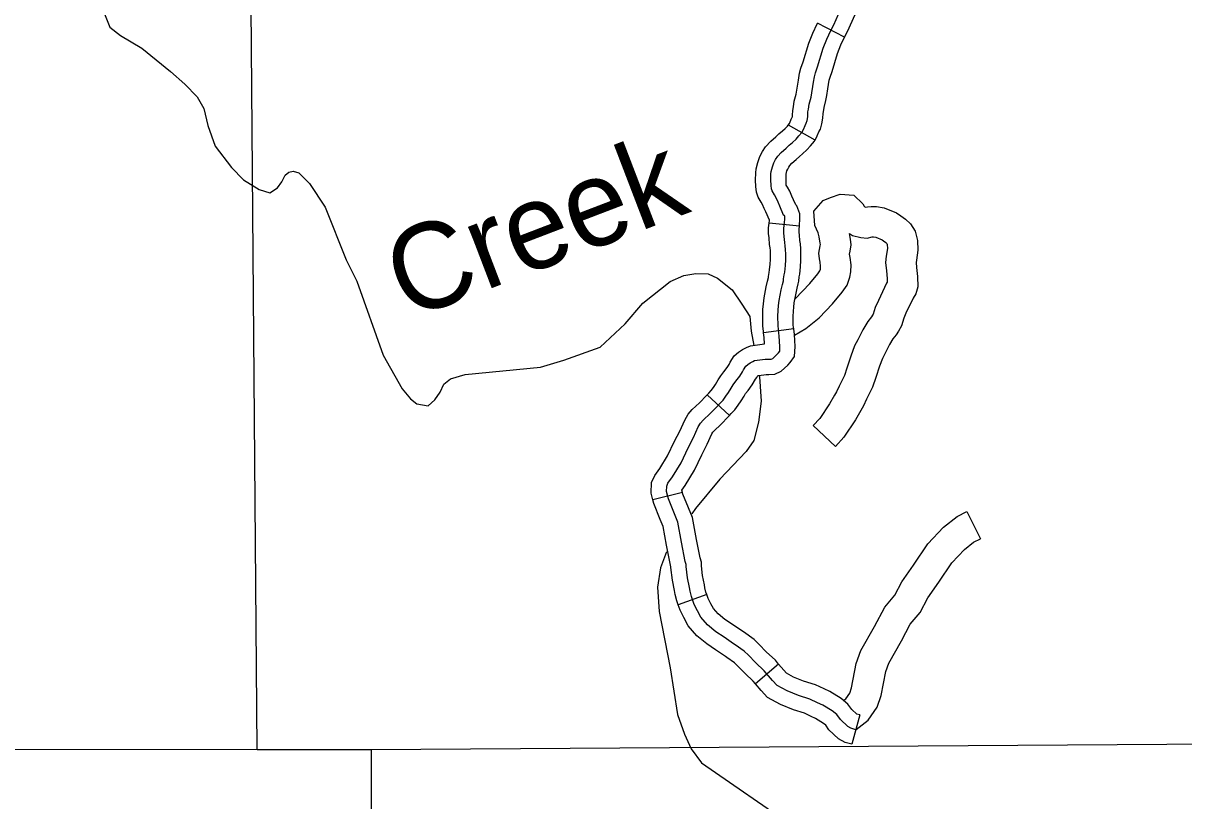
# Model space of a CAD drawing. Extents: x 1377389 to 1380723, y 1168351 to 1170484.
# Drawn here: x 1379073.5 to 1379187.9, y 1169316 to 1169392.7 of the extents above; entities that cross this region are included whole.
import ezdxf

# ---------------------------------------------------------------- set-up
doc = ezdxf.new("R2010")
doc.units = 0
doc.layers.add('B_Fill', color=7, linetype='Continuous')

msp = doc.modelspace()

# ---------------------------------------------------------------- linework, layer by layer
at = {"layer": 'B_Fill'}
for p, q in [((1379154.45, 1169391.32), (1379151.79, 1169392.71)), ((1379151.56, 1169381.19), (1379148.94, 1169382.66)), ((1379150.01, 1169372.69), (1379147.02, 1169372.99)), ((1379149.45, 1169362.56), (1379146.48, 1169362.16)), ((1379143.13, 1169354.03), (1379140.91, 1169356.05)), ((1379138.48, 1169346.44), (1379135.57, 1169345.71)), ((1379140.89, 1169336.36), (1379138.06, 1169335.36)), ((1379147.96, 1169329.51), (1379145.69, 1169327.55)), ((1379155.98, 1169324.49), (1379155.19, 1169321.6))]:
    msp.add_line(p, q, dxfattribs=at)
for points in [[(1379096.54, 1169321.07), (1379095.67, 1169427.01)], [(1379154.45, 1169391.32), (1379154.75, 1169391.9), (1379155.51, 1169393.57), (1379156.02, 1169395.05), (1379156.49, 1169396.06), (1379157.07, 1169396.94), (1379157.73, 1169397.84), (1379158.55, 1169398.83), (1379159.19, 1169399.71), (1379159.22, 1169399.74), (1379159.07, 1169399.67)], [(1379081.35, 1169393.95), (1379082, 1169392.31), (1379083.06, 1169391.48), (1379085.16, 1169390.23), (1379088, 1169387.93), (1379089.4, 1169386.7), (1379090.61, 1169385.45), (1379091.29, 1169384.31), (1379091.66, 1169382.62), (1379092.4, 1169380.57), (1379094.02, 1169378.47), (1379095.2, 1169377.27), (1379096.72, 1169376.3), (1379097.79, 1169375.97), (1379098.55, 1169376.47), (1379098.97, 1169377.05), (1379099.29, 1169377.72), (1379099.66, 1169378.01), (1379100.08, 1169378.12), (1379100.66, 1169377.96), (1379101.71, 1169376.91), (1379103.26, 1169374.56), (1379105.32, 1169369.38), (1379106.38, 1169367.27), (1379108.96, 1169359.98), (1379110.84, 1169356.64), (1379111.65, 1169355.66), (1379112.29, 1169355.18), (1379113.41, 1169354.96), (1379114.05, 1169355.56), (1379114.6, 1169356.31), (1379114.94, 1169357.12), (1379115.62, 1169357.64), (1379117.06, 1169358.07), (1379124.48, 1169358.8), (1379126.77, 1169359.49), (1379130.38, 1169360.76), (1379132.82, 1169363.06), (1379134.58, 1169365.09), (1379137.28, 1169367.24), (1379138.6, 1169367.82), (1379139.81, 1169368.02), (1379141.03, 1169367.99), (1379141.94, 1169367.58), (1379143.39, 1169366.41), (1379144.35, 1169365.01), (1379145.13, 1169363.78), (1379145.27, 1169362.34), (1379145.53, 1169360.91)], [(1379148.07, 1169374.68), (1379147.91, 1169375.05), (1379147.71, 1169375.5), (1379147.55, 1169375.79), (1379147.32, 1169376.18), (1379147.26, 1169376.37), (1379147.22, 1169376.71), (1379147.19, 1169377.26), (1379147.21, 1169377.85), (1379147.23, 1169378.09), (1379147.35, 1169378.56), (1379147.48, 1169378.94), (1379147.67, 1169379.28), (1379147.87, 1169379.59), (1379148.23, 1169379.97), (1379148.7, 1169380.38), (1379149.01, 1169380.68), (1379149.34, 1169380.96), (1379149.68, 1169381.27), (1379149.97, 1169381.59), (1379150.25, 1169381.92), (1379150.42, 1169382.23), (1379150.57, 1169382.61), (1379150.69, 1169382.85), (1379150.78, 1169383.12), (1379150.84, 1169383.49), (1379150.85, 1169383.96), (1379150.9, 1169384.23), (1379150.98, 1169384.72), (1379151.16, 1169385.4), (1379151.24, 1169385.84), (1379151.35, 1169386.46), (1379151.4, 1169386.88), (1379151.49, 1169387.43), (1379151.6, 1169387.83), (1379151.81, 1169388.42), (1379152.36, 1169390.23), (1379152.73, 1169391.15), (1379153.1, 1169391.98), (1379153.4, 1169392.55), (1379154.11, 1169394.13)], [(1379148.94, 1169382.66), (1379149.06, 1169382.87), (1379149.2, 1169383.23), (1379149.3, 1169383.43), (1379149.32, 1169383.47), (1379149.34, 1169383.63), (1379149.36, 1169384.11), (1379149.42, 1169384.47), (1379149.51, 1169385.03), (1379149.69, 1169385.72), (1379149.76, 1169386.1), (1379149.86, 1169386.68), (1379149.91, 1169387.1), (1379150.03, 1169387.77), (1379150.17, 1169388.28), (1379150.39, 1169388.89), (1379150.95, 1169390.73), (1379151.35, 1169391.73), (1379151.75, 1169392.63), (1379151.79, 1169392.71)], [(1379151.56, 1169381.19), (1379151.78, 1169381.59), (1379151.94, 1169381.99), (1379152.08, 1169382.27), (1379152.24, 1169382.77), (1379152.34, 1169383.34), (1379152.35, 1169383.8), (1379152.38, 1169383.98), (1379152.45, 1169384.41), (1379152.63, 1169385.08), (1379152.71, 1169385.59), (1379152.83, 1169386.24), (1379152.88, 1169386.66), (1379152.96, 1169387.1), (1379153.04, 1169387.38), (1379153.24, 1169387.95), (1379153.78, 1169389.73), (1379154.11, 1169390.56), (1379154.45, 1169391.33), (1379154.45, 1169391.32)], [(1379147.02, 1169372.99), (1379147.05, 1169373.26), (1379147.05, 1169373.27), (1379146.69, 1169374.09), (1379146.54, 1169374.45), (1379146.36, 1169374.84), (1379146.25, 1169375.05), (1379145.94, 1169375.55), (1379145.78, 1169376.06), (1379145.72, 1169376.59), (1379145.69, 1169377.24), (1379145.71, 1169377.95), (1379145.75, 1169378.36), (1379145.91, 1169378.98), (1379146.1, 1169379.55), (1379146.39, 1169380.06), (1379146.68, 1169380.52), (1379147.19, 1169381.06), (1379147.69, 1169381.49), (1379148, 1169381.79), (1379148.35, 1169382.09), (1379148.62, 1169382.33), (1379148.83, 1169382.57), (1379149.01, 1169382.78), (1379148.94, 1169382.65)], [(1379150.01, 1169372.69), (1379150.03, 1169372.91), (1379150.07, 1169373.25), (1379150.07, 1169373.51), (1379150.07, 1169373.91), (1379149.77, 1169374.71), (1379149.66, 1169374.79), (1379149.44, 1169375.28), (1379149.28, 1169375.66), (1379149.06, 1169376.16), (1379148.85, 1169376.54), (1379148.72, 1169376.75), (1379148.72, 1169376.82), (1379148.7, 1169377.28), (1379148.71, 1169377.76), (1379148.71, 1169377.82), (1379148.79, 1169378.14), (1379148.86, 1169378.33), (1379148.96, 1169378.51), (1379149.06, 1169378.67), (1379149.27, 1169378.89), (1379149.71, 1169379.27), (1379150.01, 1169379.56), (1379150.32, 1169379.83), (1379150.75, 1169380.21), (1379151.1, 1169380.61), (1379151.49, 1169381.06), (1379151.56, 1169381.2)], [(1379149.58, 1169365.52), (1379151.04, 1169367.03), (1379151.83, 1169367.99), (1379152.02, 1169368.28), (1379152.09, 1169368.46), (1379152.1, 1169368.51), (1379152.11, 1169368.75), (1379152.06, 1169369.13), (1379151.99, 1169369.48), (1379151.92, 1169370.04), (1379152.07, 1169370.76), (1379152.09, 1169370.9), (1379152.07, 1169371.01), (1379151.97, 1169371.65), (1379151.85, 1169372.04), (1379151.54, 1169372.75), (1379151.44, 1169374.18), (1379152.37, 1169375.22), (1379153.07, 1169375.51), (1379154.04, 1169375.84), (1379155.37, 1169375.74), (1379156.26, 1169374.9), (1379156.41, 1169374.66), (1379156.51, 1169374.56), (1379156.51, 1169374.56), (1379156.72, 1169374.61), (1379157.1, 1169374.64), (1379157.6, 1169374.64), (1379158.38, 1169374.5), (1379159.6, 1169374.01), (1379160.02, 1169373.72), (1379160.48, 1169373.39), (1379160.97, 1169372.91), (1379161.44, 1169372.2), (1379161.67, 1169371.29), (1379161.69, 1169370.31), (1379161.55, 1169369.35), (1379161.52, 1169369.1), (1379161.57, 1169368.61), (1379161.67, 1169367.74), (1379161.69, 1169366.72), (1379161.51, 1169366.01), (1379161.23, 1169365.6), (1379160.52, 1169364.1), (1379160.31, 1169363.63), (1379160.08, 1169362.86), (1379159.79, 1169362.35), (1379159.55, 1169361.98), (1379159.24, 1169361.59), (1379158.91, 1169361.03), (1379158.45, 1169360.1), (1379158.2, 1169359.64), (1379157.91, 1169358.88), (1379157.55, 1169357.76), (1379157.23, 1169356.8), (1379156.63, 1169355.62), (1379156.35, 1169354.98), (1379156.08, 1169354.52), (1379155.54, 1169353.6), (1379154.39, 1169351.87), (1379153.56, 1169350.98)], [(1379155.59, 1169323.04), (1379155.1, 1169323.18), (1379154.78, 1169323.36), (1379154.06, 1169324.03), (1379153.7, 1169324.53), (1379153.25, 1169324.89), (1379152.31, 1169325.47), (1379151.81, 1169325.7), (1379151.05, 1169326.06), (1379149.92, 1169326.42), (1379148.8, 1169326.87), (1379147.81, 1169327.41), (1379147.36, 1169327.9), (1379146.55, 1169328.85), (1379145.7, 1169329.66), (1379144.98, 1169330.38), (1379144.58, 1169330.77), (1379143.68, 1169331.42), (1379143.53, 1169331.51), (1379142.58, 1169332.16), (1379141.77, 1169332.7), (1379140.94, 1169333.38), (1379140.29, 1169334.14), (1379139.95, 1169334.77), (1379139.64, 1169335.4), (1379139.37, 1169336.17), (1379139.23, 1169336.69), (1379139.16, 1169337.05), (1379138.98, 1169338.02), (1379138.85, 1169339.12), (1379138.85, 1169339.32), (1379138.76, 1169339.61), (1379138.4, 1169341.53), (1379138.04, 1169343.51), (1379137.68, 1169344.34), (1379137.09, 1169345.8), (1379136.91, 1169346.52), (1379136.93, 1169347.06), (1379137.05, 1169347.34), (1379137.51, 1169347.96), (1379138.34, 1169349.34), (1379139.05, 1169350.82), (1379139.57, 1169351.84), (1379140.04, 1169352.89), (1379140.25, 1169353.25), (1379140.53, 1169353.56), (1379141.2, 1169354.21), (1379141.93, 1169354.94), (1379142.19, 1169355.23), (1379142.48, 1169355.54), (1379142.76, 1169355.92), (1379143.01, 1169356.29), (1379143.28, 1169356.73), (1379143.49, 1169357.05), (1379143.76, 1169357.41), (1379144.13, 1169357.89), (1379144.39, 1169358.32), (1379144.5, 1169358.53), (1379144.72, 1169358.89), (1379144.93, 1169359.06), (1379145.17, 1169359.23), (1379145.41, 1169359.36), (1379145.59, 1169359.43), (1379146.64, 1169359.58), (1379146.98, 1169359.57), (1379147.22, 1169359.58), (1379147.38, 1169359.65), (1379147.8, 1169360.04), (1379147.95, 1169360.2), (1379148.07, 1169360.37), (1379148.09, 1169360.81), (1379148.03, 1169361.86), (1379147.95, 1169362.5), (1379147.91, 1169362.91), (1379147.9, 1169363.82), (1379147.92, 1169364.39), (1379147.96, 1169364.87), (1379148.03, 1169365.37), (1379148.22, 1169366.4), (1379148.34, 1169366.93), (1379148.43, 1169367.31), (1379148.46, 1169367.5), (1379148.51, 1169367.9), (1379148.56, 1169368.17), (1379148.64, 1169368.8), (1379148.67, 1169369.37), (1379148.67, 1169369.54), (1379148.67, 1169369.92), (1379148.65, 1169370.38), (1379148.62, 1169370.76), (1379148.56, 1169371.08), (1379148.51, 1169371.66), (1379148.48, 1169372.03), (1379148.48, 1169372.47), (1379148.54, 1169373.08), (1379148.57, 1169373.35), (1379148.57, 1169373.51), (1379148.57, 1169373.64), (1379148.54, 1169373.74), (1379148.46, 1169373.78), (1379148.07, 1169374.68)], [(1379146.48, 1169362.16), (1379146.46, 1169362.33), (1379146.41, 1169362.83), (1379146.4, 1169363.84), (1379146.42, 1169364.48), (1379146.47, 1169365.04), (1379146.55, 1169365.62), (1379146.75, 1169366.7), (1379146.88, 1169367.26), (1379146.96, 1169367.62), (1379146.98, 1169367.73), (1379147.03, 1169368.13), (1379147.08, 1169368.4), (1379147.14, 1169368.94), (1379147.17, 1169369.42), (1379147.17, 1169369.54), (1379147.17, 1169369.88), (1379147.15, 1169370.29), (1379147.13, 1169370.57), (1379147.07, 1169370.88), (1379147.02, 1169371.53), (1379146.98, 1169371.96), (1379146.98, 1169372.54), (1379147.02, 1169372.99)], [(1379149.45, 1169362.56), (1379149.44, 1169362.67), (1379149.41, 1169362.99), (1379149.4, 1169363.8), (1379149.42, 1169364.3), (1379149.45, 1169364.7), (1379149.51, 1169365.13), (1379149.69, 1169366.1), (1379149.8, 1169366.59), (1379149.89, 1169367), (1379149.95, 1169367.26), (1379150, 1169367.68), (1379150.05, 1169367.95), (1379150.13, 1169368.67), (1379150.17, 1169369.32), (1379150.17, 1169369.54), (1379150.17, 1169369.97), (1379150.15, 1169370.47), (1379150.11, 1169370.95), (1379150.05, 1169371.29), (1379150.01, 1169371.8), (1379149.98, 1169372.11), (1379149.98, 1169372.39), (1379150.01, 1169372.69)], [(1379149.54, 1169361.94), (1379150.66, 1169362.6), (1379151.96, 1169363.66), (1379153.29, 1169365.03), (1379154.24, 1169366.19), (1379154.71, 1169366.89), (1379154.99, 1169367.66), (1379155.09, 1169368.18), (1379155.12, 1169368.89), (1379155.02, 1169369.61), (1379154.96, 1169369.94), (1379155.02, 1169370.24), (1379155.11, 1169370.85), (1379155.05, 1169371.41), (1379154.96, 1169371.98), (1379155.25, 1169371.77), (1379156.06, 1169371.56), (1379156.71, 1169371.52), (1379157.19, 1169371.63), (1379157.23, 1169371.64), (1379157.33, 1169371.64), (1379157.54, 1169371.6), (1379158.17, 1169371.35), (1379158.31, 1169371.25), (1379158.55, 1169371.08), (1379158.63, 1169371), (1379158.65, 1169370.97), (1379158.67, 1169370.88), (1379158.69, 1169370.49), (1379158.58, 1169369.74), (1379158.5, 1169369.11), (1379158.59, 1169368.29), (1379158.67, 1169367.54), (1379158.68, 1169367.17), (1379158.61, 1169367.06), (1379157.8, 1169365.37), (1379157.49, 1169364.68), (1379157.3, 1169364.03), (1379157.23, 1169363.91), (1379157.12, 1169363.74), (1379156.76, 1169363.29), (1379156.27, 1169362.46), (1379155.78, 1169361.48), (1379155.46, 1169360.88), (1379155.08, 1169359.87), (1379154.7, 1169358.7), (1379154.45, 1169357.96), (1379153.92, 1169356.91), (1379153.67, 1169356.35), (1379153.49, 1169356.03), (1379152.99, 1169355.18), (1379152.03, 1169353.73), (1379151.37, 1169353.03), (1379153.56, 1169350.98)], [(1379140.91, 1169356.05), (1379141.09, 1169356.24), (1379141.32, 1169356.49), (1379141.53, 1169356.78), (1379141.74, 1169357.09), (1379142.01, 1169357.53), (1379142.26, 1169357.92), (1379142.56, 1169358.32), (1379142.88, 1169358.74), (1379143.08, 1169359.06), (1379143.19, 1169359.28), (1379143.57, 1169359.89), (1379144.02, 1169360.26), (1379144.39, 1169360.52), (1379144.78, 1169360.72), (1379145.2, 1169360.89), (1379146.56, 1169361.08), (1379146.58, 1169361.08), (1379146.54, 1169361.72), (1379146.48, 1169362.16)], [(1379143.13, 1169354.03), (1379143.3, 1169354.21), (1379143.63, 1169354.58), (1379143.99, 1169355.05), (1379144.27, 1169355.48), (1379144.55, 1169355.93), (1379144.71, 1169356.19), (1379144.95, 1169356.5), (1379145.37, 1169357.04), (1379145.69, 1169357.59), (1379145.8, 1169357.78), (1379145.86, 1169357.88), (1379145.96, 1169357.95), (1379146, 1169357.97), (1379146.72, 1169358.08), (1379147, 1169358.07), (1379147.59, 1169358.1), (1379148.22, 1169358.39), (1379148.86, 1169358.97), (1379149.11, 1169359.25), (1379149.54, 1169359.85), (1379149.6, 1169360.82), (1379149.53, 1169362), (1379149.45, 1169362.56)], [(1379146.06, 1169357.98), (1379146.09, 1169357.82), (1379146.25, 1169355.43), (1379145.99, 1169353.38), (1379145.53, 1169351.56), (1379144.75, 1169350.46), (1379142.18, 1169347.74), (1379139.78, 1169344.84), (1379139.4, 1169344.32)], [(1379135.57, 1169345.71), (1379135.41, 1169346.36), (1379135.43, 1169347.4), (1379135.75, 1169348.1), (1379136.26, 1169348.79), (1379137.02, 1169350.05), (1379137.71, 1169351.49), (1379138.22, 1169352.48), (1379138.7, 1169353.57), (1379139.03, 1169354.14), (1379139.45, 1169354.61), (1379140.15, 1169355.28), (1379140.85, 1169355.98), (1379140.91, 1169356.05)], [(1379138.48, 1169346.44), (1379138.42, 1169346.67), (1379138.76, 1169347.12), (1379139.67, 1169348.63), (1379140.39, 1169350.15), (1379140.93, 1169351.19), (1379141.37, 1169352.2), (1379141.47, 1169352.37), (1379141.61, 1169352.52), (1379142.26, 1169353.14), (1379143.02, 1169353.91), (1379143.13, 1169354.03)], [(1379140.89, 1169336.36), (1379140.8, 1169336.61), (1379140.7, 1169337.02), (1379140.64, 1169337.32), (1379140.47, 1169338.24), (1379140.35, 1169339.21), (1379140.35, 1169339.55), (1379140.22, 1169339.97), (1379139.87, 1169341.8), (1379139.48, 1169343.95), (1379139.06, 1169344.92), (1379138.53, 1169346.27), (1379138.48, 1169346.44)], [(1379138.06, 1169335.36), (1379137.93, 1169335.73), (1379137.77, 1169336.36), (1379137.69, 1169336.77), (1379137.5, 1169337.79), (1379137.35, 1169339.03), (1379137.35, 1169339.1), (1379137.3, 1169339.25), (1379136.92, 1169341.25), (1379136.59, 1169343.07), (1379136.29, 1169343.77), (1379135.66, 1169345.34), (1379135.57, 1169345.71)], [(1379154.41, 1169325.94), (1379154.59, 1169326.07), (1379154.98, 1169326.63), (1379155.16, 1169327.17), (1379155.62, 1169329.55), (1379156.08, 1169330.86), (1379157.43, 1169333.23), (1379158.43, 1169335.12), (1379159.41, 1169336.29), (1379160.12, 1169337.63), (1379161.28, 1169339.27), (1379162.69, 1169341.36), (1379164.24, 1169343.02), (1379165.56, 1169344.07), (1379166.54, 1169344.56), (1379167.88, 1169341.87)], [(1379155.6, 1169323.07), (1379156.78, 1169323.97), (1379157.69, 1169325.27), (1379158.07, 1169326.41), (1379158.53, 1169328.77), (1379158.82, 1169329.61), (1379160.07, 1169331.79), (1379160.93, 1169333.44), (1379161.91, 1169334.6), (1379162.68, 1169336.05), (1379163.75, 1169337.57), (1379165.04, 1169339.48), (1379166.28, 1169340.8), (1379167.18, 1169341.52), (1379167.88, 1169341.87)], [(1379136.92, 1169340.59), (1379136.33, 1169338.99), (1379136.03, 1169337.1), (1379136.17, 1169334.68), (1379137.28, 1169329.15), (1379137.98, 1169324.53), (1379138.68, 1169322.59), (1379139.34, 1169321.15), (1379140.36, 1169319.76), (1379149.6, 1169313.4), (1379153.85, 1169310.23)], [(1379147.96, 1169329.51), (1379147.64, 1169329.88), (1379146.74, 1169330.73), (1379146.03, 1169331.44), (1379145.56, 1169331.92), (1379144.5, 1169332.68), (1379144.33, 1169332.78), (1379143.42, 1169333.4), (1379142.66, 1169333.91), (1379141.99, 1169334.46), (1379141.53, 1169334.99), (1379141.28, 1169335.46), (1379141.02, 1169335.99), (1379140.89, 1169336.36)], [(1379145.69, 1169327.55), (1379145.46, 1169327.81), (1379144.65, 1169328.59), (1379143.92, 1169329.32), (1379143.61, 1169329.62), (1379142.87, 1169330.16), (1379142.73, 1169330.24), (1379141.74, 1169330.92), (1379140.88, 1169331.49), (1379139.89, 1169332.3), (1379139.04, 1169333.29), (1379138.62, 1169334.09), (1379138.25, 1169334.82), (1379138.06, 1169335.36)], [(1379155.98, 1169324.49), (1379155.68, 1169324.57), (1379155.19, 1169325.03), (1379154.8, 1169325.57), (1379154.12, 1169326.12), (1379153.02, 1169326.8), (1379152.44, 1169327.06), (1379151.6, 1169327.46), (1379150.43, 1169327.83), (1379149.44, 1169328.23), (1379148.75, 1169328.61), (1379148.49, 1169328.9), (1379147.96, 1169329.51)], [(1379155.19, 1169321.6), (1379154.52, 1169321.78), (1379153.88, 1169322.14), (1379152.93, 1169323.04), (1379152.61, 1169323.48), (1379152.38, 1169323.66), (1379151.6, 1169324.15), (1379151.18, 1169324.34), (1379150.5, 1169324.66), (1379149.42, 1169325.01), (1379148.16, 1169325.51), (1379146.87, 1169326.21), (1379146.24, 1169326.91), (1379145.69, 1169327.55)], [(1378969.38, 1169321.13), (1378989.27, 1169321.09), (1379001.13, 1169321.14), (1379096.54, 1169321.07), (1379107.79, 1169321.09), (1379200.98, 1169321.71), (1379211.33, 1169321.71), (1379309.03, 1169322.34), (1379318.77, 1169322.31), (1379331.4, 1169322.31)], [(1379107.79, 1169321.09), (1379107.87, 1169151.89)]]:
    msp.add_lwpolyline(points, dxfattribs=at)

# ---------------------------------------------------------------- texts
msp.add_text('Creek', height=8.448, rotation=20.9515, dxfattribs=at).set_placement((1379111.32, 1169363.38))

doc.saveas('drawing.dxf')
